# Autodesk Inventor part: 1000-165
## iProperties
Created: 2012-08
Part Number: 1000-165
Document SubType Name: Modeling
Designer: Administrator
Density: 7.85 g/cm^3
Material: Steel
Mass: 20.9041 g
Surface Area: 21.5742 cm^2
Volume: 2.66294 cm^3
Author: Administrator
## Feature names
1. Base1
